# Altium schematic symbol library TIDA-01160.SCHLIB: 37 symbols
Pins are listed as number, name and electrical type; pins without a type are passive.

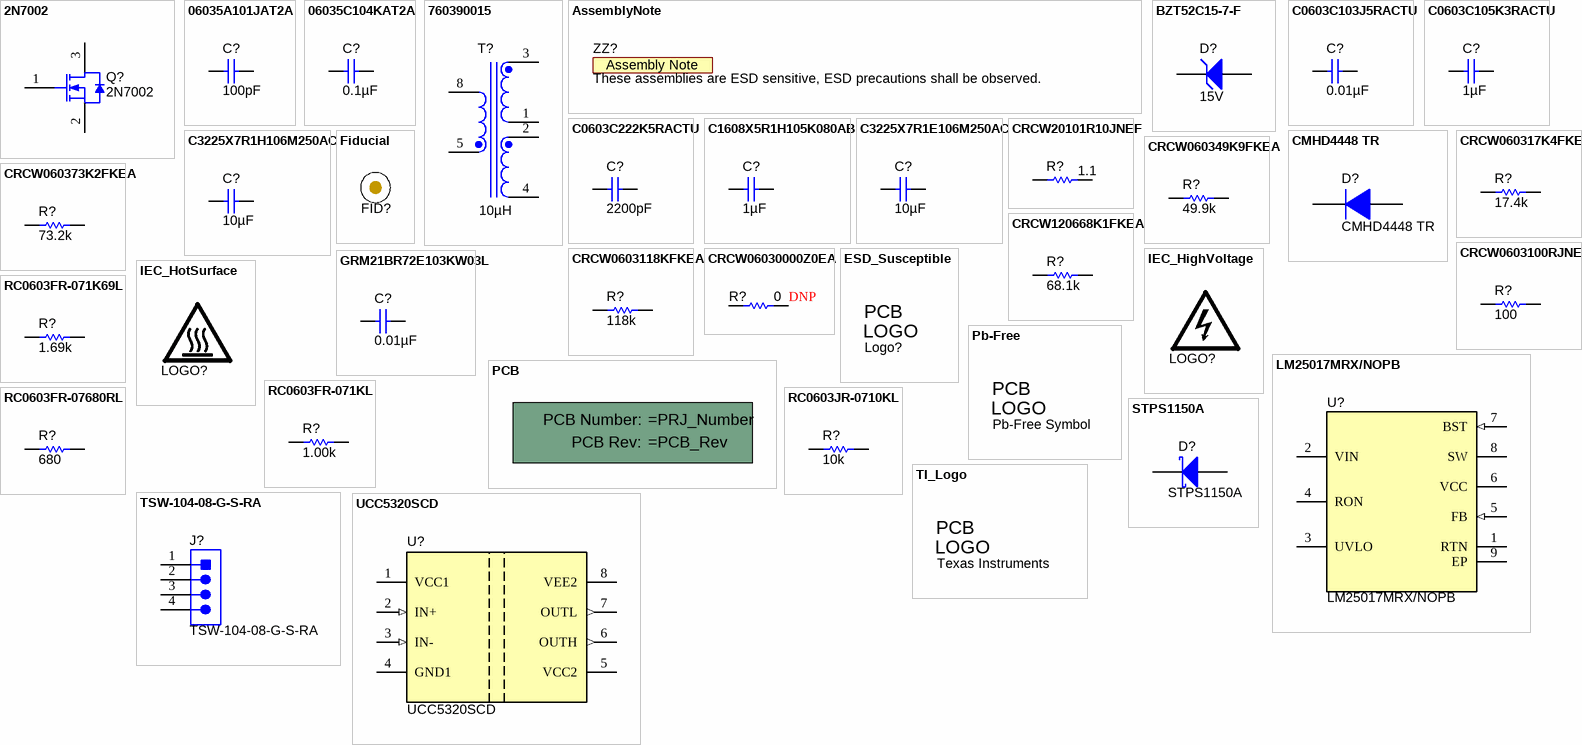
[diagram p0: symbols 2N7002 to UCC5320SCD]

## 2N7002
designator Q?
MOSFET, N-CH, 60 V, 115 A, SOT-23; Manufacturer: Fairchild Semiconductor; Alternate Manufacturer: None; U/M: EA; ChType: N; Value: 60V; VdsMax_V: 60; Value1: ? ohm; Value2: ? nC; Vgs_V: 20; IdsMax_A: 115; SizeAreaWB_mm2: 14; SizeArea_mm2: 7.5; SizeX_mm: 2.5; SizeY_mm: 3; SizeZ_mm: 1.1; AEC Category: Q101
footprint SOT-23
footprint SOT-23M
footprint SOT-23L
pins: 1 G, 2 S, 3 D

## 06035A101JAT2A
designator C?  ValueDisplayed: 100pF  (hidden comment: 06035A101JAT2A)
CAP, CERM, 100 pF, 50 V, +/- 5%, C0G/NP0, 0603; Manufacturer: AVX; Polarized: N; CompType: Capacitor; Value: 100pF; U/M: EA; Cap_F: 0.0000000001; Tolerance_%: 5; ESR_ohm: 0.119; Value1: 0.119 ohm; VDC_V: 50; Value2: 50V; TaMin_C: -55; TaMax_C: 125; Cap_Case: 0603; SizeArea_mm2: 1.28; SizeAreaWB_mm2: 4.68; SizeX_mm: 1.6; SizeY_mm: 0.8; SizeZ_mm: 1; AEC Category: Q200
signal-integrity model Cap
simulation model Cap
footprint 0603
footprint 0603M
footprint 0603L
footprint 0603_HV
footprint 0603S
pins: 1, 2

## 06035C104KAT2A
designator C?  ValueDisplayed: 0.1µF  (hidden comment: 06035C104KAT2A)
CAP, CERM, 0.1 µF, 50 V, +/- 10%, X7R, 0603; Manufacturer: AVX; Polarized: N; CompType: Capacitor; Value: 0.1uF; U/M: EA; Cap_F: 0.0000001; Tolerance_%: 10; Value1: Unknown; VDC_V: 50; Value2: 50V; TaMin_C: -55; TaMax_C: 125; Cap_Case: 0603; SizeArea_mm2: 1.28; SizeAreaWB_mm2: 4.68; SizeX_mm: 1.6; SizeY_mm: 0.8; SizeZ_mm: 1; AEC Category: Q200
signal-integrity model Cap
simulation model Cap
footprint 0603
footprint 0603M
footprint 0603L
footprint 0603_HV
footprint 0603S
pins: 1, 2

## 760390015
designator T?, comment ValueDisplayed: 10µH  (hidden comment: 750343468Rev02)
Transformer, 10µH, SMT; Manufacturer: Wurth Elektronik; SymbolCreator: Altium; Lp: 475; DCR_ohm: 0.35; Ns1toNp: 2; Rs1: 0.57
footprint WURTH_750315248 (TRANSFORMER, SMD-8P)
footprint WURTH_750315248 (Footprint not found)
pins: 1, 2, 3, 4, 5, 8

## AssemblyNote
designator ZZ?, comment These assemblies are ESD sensitive, ESD precautions shall be observed.  (no BOM)
SymbolCreator: codlsc; CompType: AssemblyNote
footprint AssemblyNote

## BZT52C15-7-F
designator D?  value 15V  (hidden comment: BZT52C15-7-F)
Diode, Zener, 15 V, 370 mW, AEC-Q101, SOD-123; Manufacturer: Diodes Inc.; SymbolCreator: a0412235; U/M: EA; Power_W: 0.37; Vz_V: 15; Value1: 0.37W; RJA_CperW: 338; AEC Category: Q101; AEC Qualified: Y
signal-integrity model Diode
footprint SOD-123
pins: 1 K, 2 A

## C0603C103J5RACTU
designator C?  ValueDisplayed: 0.01µF  (hidden comment: C0603C103J5RACTU)
CAP, CERM, 0.01 µF, 50 V, +/- 5%, X7R, 0603; Manufacturer: Kemet; Polarized: N; CompType: Capacitor; Value: 0.01uF; U/M: EA; Cap_F: 0.00000001; Tolerance_%: 5; Value1: Unknown; VDC_V: 50; Value2: 50V; TaMin_C: -55; TaMax_C: 125; Cap_Case: 0603; SizeArea_mm2: 1.28; SizeAreaWB_mm2: 4.68; SizeX_mm: 1.6; SizeY_mm: 0.8; SizeZ_mm: 1; AEC Category: Q200
signal-integrity model Cap
simulation model Cap
footprint 0603
footprint 0603M
footprint 0603L
footprint 0603_HV
footprint 0603S
pins: 1, 2

## C0603C105K3RACTU
designator C?  ValueDisplayed: 1µF  (hidden comment: C0603C105K3RACTU)
CAP, CERM, 1 µF, 25 V, +/- 10%, X7R, 0603; Manufacturer: Kemet; Polarized: N; CompType: Capacitor; Value: 1uF; U/M: EA; Cap_F: 0.000001; Tolerance_%: 10; Value1: Unknown; VDC_V: 25; Value2: 25V; TaMin_C: -55; TaMax_C: 125; Cap_Case: 0603; SizeArea_mm2: 1.28; SizeAreaWB_mm2: 4.68; SizeX_mm: 1.6; SizeY_mm: 0.8; SizeZ_mm: 1; AEC Category: Q200
signal-integrity model Cap
simulation model Cap
footprint 0603
footprint 0603M
footprint 0603L
footprint 0603_HV
footprint 0603S
pins: 1, 2

## C0603C222K5RACTU
designator C?  ValueDisplayed: 2200pF  (hidden comment: C0603C222K5RACTU)
CAP, CERM, 2200 pF, 50 V, +/- 10%, X7R, 0603; Manufacturer: Kemet; Polarized: N; CompType: Capacitor; Value: 2200pF; U/M: EA; Cap_F: 0.0000000022; Tolerance_%: 10; Value1: Unknown; VDC_V: 50; Value2: 50V; TaMin_C: -55; TaMax_C: 125; Cap_Case: 0603; SizeArea_mm2: 1.28; SizeAreaWB_mm2: 4.68; SizeX_mm: 1.6; SizeY_mm: 0.8; SizeZ_mm: 1; AEC Category: Q200
signal-integrity model Cap
simulation model Cap
footprint 0603
footprint 0603M
footprint 0603L
footprint 0603_HV
footprint 0603S
pins: 1, 2

## C1608X5R1H105K080AB
designator C?  ValueDisplayed: 1µF  (hidden comment: C1608X5R1H105K080AB)
CAP, CERM, 1 µF, 50 V, +/- 10%, X5R, 0603; Manufacturer: TDK; Polarized: N; CompType: Capacitor; Value: 1uF; U/M: EA; Cap_F: 0.000001; Tolerance_%: 10; ESR_ohm: 0.005522; Value1: 0.005522 ohm; VDC_V: 50; Value2: 50V; IRMS_A: 2.21617; TaMin_C: -55; TaMax_C: 85; Cap_Case: 0603; SizeArea_mm2: 1.28; SizeAreaWB_mm2: 4.68; SizeX_mm: 1.6; SizeY_mm: 0.8; SizeZ_mm: 1; AEC Category: Q200
signal-integrity model Cap
simulation model Cap
footprint 0603
footprint 0603M
footprint 0603L
footprint 0603_HV
footprint 0603S
pins: 1, 2

## C3225X7R1E106M250AC
designator C?  ValueDisplayed: 10µF  (hidden comment: C3225X7R1E106M250AC)
CAP, CERM, 10 µF, 25 V, +/- 20%, X7R, 1210; Manufacturer: TDK; Polarized: N; CompType: Capacitor; Value: 10uF; U/M: EA; Cap_F: 0.00001; Tolerance_%: 20; Value1: Unknown; VDC_V: 25; Value2: 25V; TaMin_C: -55; TaMax_C: 125; Cap_Case: 1210; SizeArea_mm2: 8; SizeAreaWB_mm2: 14.7; SizeX_mm: 3.2; SizeY_mm: 2.5; SizeZ_mm: 2.8; AEC Category: Q200
signal-integrity model Cap
simulation model Cap
footprint 1210_280
pins: 1, 2

## C3225X7R1H106M250AC
designator C?  ValueDisplayed: 10µF  (hidden comment: C3225X7R1H106M250AC)
CAP, CERM, 10 µF, 50 V, +/- 20%, X7R, 1210; Manufacturer: TDK; Polarized: N; CompType: Capacitor; Value: 10uF; U/M: EA; Cap_F: 0.00001; Tolerance_%: 20; Value1: Unknown; VDC_V: 50; Value2: 50V; TaMin_C: -55; TaMax_C: 125; Cap_Case: 1210; SizeArea_mm2: 8; SizeAreaWB_mm2: 14.7; SizeX_mm: 3.2; SizeY_mm: 2.5; SizeZ_mm: 2.8; AEC Category: Q200
signal-integrity model Cap
simulation model Cap
footprint 1210_280
pins: 1, 2

## CMHD4448 TR
designator D?
Diode, Switching, 100 V, 0.25 A, SOD-123; Manufacturer: Central Semiconductor; U/M: EA; Vf_V: 1; Value: 100V; Value1: 0.25A; Value2: 1V; Io_A: 0.25; Vr_V: 100; TJmax_C: 150; SizeAreaWB_mm2: 13.095; SizeArea_mm2: 6.545; SizeX_mm: 3.85; SizeY_mm: 1.7; SizeZ_mm: 1.35; AEC Category: Q101
signal-integrity model Diode
footprint SOD-123 (On Semi recommended land pattern)
pins: 1 K, 2 A

## CRCW20101R10JNEF
designator R?  ValueDisplayed: 1.1  (hidden comment: CRCW20101R10JNEF)
RES, 1.1, 5%, 0.75 W, AEC-Q200 Grade 0, 2010; Manufacturer: Vishay-Dale; CompType: Resistor; Value: 1.1; Value_Code: 1R10; Tolerance_%: 5; Power_W: 0.75; Value2: 0.75W; VDC_V: 400; TempCo: 200 ppm/C; SizeArea_mm2: 12.5; SizeY_mm: 2.5; SizeZ_mm: 1.66; EIA_Code: E24; U/M: EA; AEC Category: Q200; AEC Qualified: Y; AEC Grade: 0
signal-integrity model Resistor
simulation model Resistor
footprint 2010
footprint 2010M
footprint 2010L
pins: 1, 2

## CRCW060317K4FKEA
designator R?  ValueDisplayed: 17.4k  (hidden comment: CRCW060317K4FKEA)
RES, 17.4 k, 1%, 0.1 W, 0603; Manufacturer: Vishay-Dale; CompType: Resistor; Value: 17.4k; Res_ohm: 17400; Value_Code: 17k4; Tolerance_%: 1; Power_W: 0.1; Value2: 0.1W; VDC_V: 75; TempCo: 100 ppm/C; SizeArea_mm2: 1.28; SizeX_mm: 1.6; SizeY_mm: 0.8; EIA_Code: E96; U/M: EA; AEC Category: Q200
signal-integrity model Resistor
simulation model Resistor
footprint 0603
footprint 0603M
footprint 0603L
footprint 0603_HV
footprint 0603S
pins: 1, 2

## CRCW060349K9FKEA
designator R?  ValueDisplayed: 49.9k  (hidden comment: CRCW060349K9FKEA)
RES, 49.9 k, 1%, 0.1 W, 0603; Manufacturer: Vishay-Dale; CompType: Resistor; Value: 49.9k; Res_ohm: 49900; Value_Code: 49k9; Tolerance_%: 1; Power_W: 0.1; Value2: 0.1W; VDC_V: 75; TempCo: 100 ppm/C; SizeArea_mm2: 1.28; SizeX_mm: 1.6; SizeY_mm: 0.8; EIA_Code: E96; U/M: EA; AEC Category: Q200
signal-integrity model Resistor
simulation model Resistor
footprint 0603
footprint 0603M
footprint 0603L
footprint 0603_HV
footprint 0603S
pins: 1, 2

## CRCW060373K2FKEA
designator R?  ValueDisplayed: 73.2k  (hidden comment: CRCW060373K2FKEA)
RES, 73.2 k, 1%, 0.1 W, 0603; Manufacturer: Vishay-Dale; CompType: Resistor; Value: 73.2k; Res_ohm: 73200; Value_Code: 73k2; Tolerance_%: 1; Power_W: 0.1; Value2: 0.1W; VDC_V: 75; TempCo: 100 ppm/C; SizeArea_mm2: 1.28; SizeX_mm: 1.6; SizeY_mm: 0.8; EIA_Code: E96; U/M: EA; AEC Category: Q200
signal-integrity model Resistor
simulation model Resistor
footprint 0603
footprint 0603M
footprint 0603L
footprint 0603_HV
footprint 0603S
pins: 1, 2

## CRCW120668K1FKEA
designator R?  ValueDisplayed: 68.1k  (hidden comment: CRCW120668K1FKEA)
RES, 68.1 k, 1%, 0.25 W, 1206; Manufacturer: Vishay-Dale; CompType: Resistor; Value: 68.1k; Res_ohm: 68100; Value_Code: 68k1; Tolerance_%: 1; Power_W: 0.25; Value2: 0.25W; VDC_V: 200; TempCo: 100 ppm/C; SizeArea_mm2: 5.12; SizeX_mm: 3.2; SizeY_mm: 1.6; SizeZ_mm: 1.35; EIA_Code: E96; U/M: EA; AEC Category: Q200
signal-integrity model Resistor
simulation model Resistor
footprint 1206
footprint 1206M
footprint 1206L
pins: 1, 2

## CRCW0603100RJNEA
designator R?  ValueDisplayed: 100  (hidden comment: CRCW0603100RJNEA)
RES, 100, 5%, 0.1 W, 0603; Manufacturer: Vishay-Dale; CompType: Resistor; Value: 100; Value_Code: 100R; Tolerance_%: 5; Power_W: 0.1; Value2: 0.1W; VDC_V: 75; TempCo: 200 ppm/C; SizeArea_mm2: 1.28; SizeX_mm: 1.6; SizeY_mm: 0.8; SizeZ_mm: 1; EIA_Code: E24; U/M: EA; AEC Category: Q200
signal-integrity model Resistor
simulation model Resistor
footprint 0603
footprint 0603M
footprint 0603L
footprint 0603_HV
footprint 0603S
pins: 1, 2

## CRCW0603118KFKEA
designator R?  ValueDisplayed: 118k  (hidden comment: CRCW0603118KFKEA)
RES, 118 k, 1%, 0.1 W, 0603; Manufacturer: Vishay-Dale; CompType: Resistor; Value: 118k; Res_ohm: 118000; Tolerance_%: 1; Power_W: 0.1; Value2: 0.1W; VDC_V: 75; TempCo: 100 ppm/C; SizeArea_mm2: 1.28; SizeX_mm: 1.6; SizeY_mm: 0.8; EIA_Code: E96; U/M: EA; AEC Category: Q200
signal-integrity model Resistor
simulation model Resistor
footprint 0603
footprint 0603M
footprint 0603L
footprint 0603_HV
footprint 0603S
pins: 1, 2

## CRCW06030000Z0EA
designator R?  ValueDisplayed: 0  Installation: DNP  (hidden comment: CRCW06030000Z0EA)
RES, 0, 5%, 0.1 W, 0603; Manufacturer: Vishay-Dale; CompType: Resistor; Value: 0; Value_Code: 0000; Tolerance_%: 5; Power_W: 0.1; Value2: 0.1W; VDC_V: 75; TempCo: 200 ppm/C; EIA_Code: E24; U/M: EA; AEC Category: Q200
signal-integrity model Resistor
simulation model Resistor
footprint 0603 (0603 from SM-752 data)
footprint 0603M
footprint 0603L
footprint 0603_HV
footprint 0603S
pins: 1, 2

## ESD_Susceptible
designator Logo?, comment ESD Susceptible  (value not drawn)  (no BOM)
ESD Susceptible Symbol; SymbolCreator: a0412235
footprint ESD_Overlay_Large
footprint ESD_Overlay_Medium
footprint ESD_Overlay_Small

## Fiducial
designator FID?  (value not drawn)
Fiducial mark.  There is nothing to buy or mount.; SymbolCreator: codlsc
footprint Fiducial10-30
footprint Fiducial10-20
footprint Fiducial15-30
footprint Fiducial20-40
footprint Fiducial6.4-20

## GRM21BR72E103KW03L
designator C?  ValueDisplayed: 0.01µF  (hidden comment: GRM21BR72E103KW03L)
CAP, CERM, 0.01 µF, 250 V, +/- 10%, X7R, 0805; Manufacturer: MuRata; Polarized: N; CompType: Capacitor; Value: 0.01uF; U/M: EA; Cap_F: 0.00000001; Tolerance_%: 10; Value1: Unknown; VDC_V: 250; Value2: 250V; TaMin_C: -55; TaMax_C: 125; Cap_Case: 0805; SizeArea_mm2: 2.5; SizeAreaWB_mm2: 6.75; SizeX_mm: 2; SizeY_mm: 1.25; SizeZ_mm: 1.45; AEC Category: Q200
signal-integrity model Cap
simulation model Cap
footprint 0805_HV
footprint 0805_HV1
footprint 0805
footprint 0805M
footprint 0805L
pins: 1, 2

## IEC_HighVoltage
designator LOGO?, comment DANGER HIGH VOLTAGE  (value not drawn)  (no BOM)
IEC 61010-1 High Voltage Warning; SymbolCreator: a0412235
footprint IEC_HighVoltage_Large
footprint IEC_HighVoltage_Medium
footprint IEC_HighVoltage_Small

## IEC_HotSurface
designator LOGO?, comment CAUTION HOT SURFACE  (value not drawn)  (no BOM)
IEC 61010-1 Hot Surface Warning; SymbolCreator: a0412235
footprint IEC_HotSurface_Large
footprint IEC_HotSurface_Medium
footprint IEC_HotSurface_Small

## LM25017MRX/NOPB
designator U?
48V, 650mA Constant On-Time Synchronous Buck Regulator, DDA0008B; Alternate PartNumber: LM25017MR/NOPB; Manufacturer: Texas Instruments; SymbolCreator: a0412235; SizeArea_mm2: 31; SizeAreaWB_mm2: 57.4; SizeX_mm: 5; SizeY_mm: 6.2; SizeZ_mm: 1.7; CompType: IC; U/M: EA
footprint DDA0008B_N
footprint DDA0008B_M
footprint DDA0008B_L
pins: 1 RTN (power), 2 VIN (power), 3 UVLO, 4 RON, 5 FB (in), 6 VCC (power), 7 BST (in), 8 SW (power), 9 EP (power)

## Pb-Free
designator Logo?, comment Pb-Free Symbol  (no BOM)
SymbolCreator: a0412235
footprint Pb-Free_Overlay_Medium
footprint Pb-Free_Overlay_Small

## PCB
designator !PCB?, comment Printed Circuit Board  (value not drawn)  (mechanical)
Manufacturer: Any; SymbolCreator: a0412235; CompType: PCB
1 alternate drawing of the same symbol

## RC0603FR-071K69L
designator R?  ValueDisplayed: 1.69k  (hidden comment: RC0603FR-071K69L)
RES, 1.69 k, 1%, 0.1 W, 0603; Manufacturer: Yageo America; CompType: Resistor; Value: 1.69k; Res_ohm: 1690; Value_Code: 1k69; Tolerance_%: 1; Power_W: 0.1; Value2: 0.1W; VDC_V: 150; TempCo: 200 ppm/C; SizeArea_mm2: 1.28; SizeX_mm: 1.6; SizeY_mm: 0.8; EIA_Code: E96; U/M: EA; AEC Category: Q200
signal-integrity model Resistor
simulation model Resistor
footprint 0603
footprint 0603M
footprint 0603L
footprint 0603_HV
footprint 0603S
pins: 1, 2

## RC0603FR-071KL
designator R?  ValueDisplayed: 1.00k  (hidden comment: RC0603FR-071KL)
RES, 1.00 k, 1%, 0.1 W, 0603; Manufacturer: Yageo America; CompType: Resistor; Value: 1.00k; Res_ohm: 1000; Value_Code: 1k00; Tolerance_%: 1; Power_W: 0.1; Value2: 0.1W; VDC_V: 150; TempCo: 200 ppm/C; SizeArea_mm2: 1.28; SizeX_mm: 1.6; SizeY_mm: 0.8; EIA_Code: E96; U/M: EA; AEC Category: Q200
signal-integrity model Resistor
simulation model Resistor
footprint 0603
footprint 0603M
footprint 0603L
footprint 0603_HV
footprint 0603S
pins: 1, 2

## RC0603FR-07680RL
designator R?  ValueDisplayed: 680  (hidden comment: RC0603FR-07680RL)
RES, 680, 1%, 0.1 W, 0603; Manufacturer: Yageo America; CompType: Resistor; Value: 680; Value_Code: 680R; Tolerance_%: 1; Power_W: 0.1; Value2: 0.1W; VDC_V: 150; TempCo: 200 ppm/C; SizeArea_mm2: 1.28; SizeX_mm: 1.6; SizeY_mm: 0.8; U/M: EA; AEC Category: Q200
signal-integrity model Resistor
simulation model Resistor
footprint 0603
footprint 0603M
footprint 0603L
footprint 0603_HV
footprint 0603S
pins: 1, 2

## RC0603JR-0710KL
designator R?  ValueDisplayed: 10k  (hidden comment: RC0603JR-0710KL)
RES, 10 k, 5%, 0.1 W, 0603; Manufacturer: Yageo America; CompType: Resistor; Value: 10k; Res_ohm: 10000; Value_Code: 10k0; Tolerance_%: 5; Power_W: 0.1; Value2: 0.1W; VDC_V: 50; TempCo: 100 ppm/C; SizeArea_mm2: 1.28; SizeX_mm: 1.6; SizeY_mm: 0.8; SizeZ_mm: 1; EIA_Code: E24; U/M: EA; AEC Category: Q200
signal-integrity model Resistor
simulation model Resistor
footprint 0603
footprint 0603M
footprint 0603L
footprint 0603_HV
footprint 0603S
pins: 1, 2

## STPS1150A
designator D?
Diode, Schottky, 150 V, 1 A, SMA; Manufacturer: STMicroelectronics; U/M: EA; Vf_V: 0.78; Value: 150V; Value1: 1A; Value2: 0.78V; Io_A: 1; Vr_V: 150; TJmax_C: 175; RJC_CperW: 30; SizeAreaWB_mm2: 37.3428; SizeArea_mm2: 16.3228; SizeX_mm: 5.59; SizeY_mm: 2.92; SizeZ_mm: 2.87; AEC Category: Q101; AEC Qualified: N
signal-integrity model Diode
footprint SMA
pins: 1 K, 2 A

## TI_Logo
designator Logo?, comment Texas Instruments  (no BOM)
Texas Instrument Corporate Signature; SymbolCreator: codlsc
footprint TI_Stacked_SolderMask_Medium
footprint TI_Stacked_SolderMask_Small
footprint TI_Stacked_Overlay_Medium
footprint TI_Stacked_Overlay_Small
footprint TI_Horizontal_SolderMask_Medium
footprint TI_Horizontal_SolderMask_Small
footprint TI_Horizontal_Overlay_Medium
footprint TI_Horizontal_Overlay_Small
footprint TI_Symbol_SolderMask_Small
footprint TI_Symbol_Overlay_Medium
footprint TI_Symbol_Overlay_Small
footprint TI_Symbol_SolderMask_Medium

## TSW-104-08-G-S-RA
designator J?
Header, 100mil, 4x1, Gold, R/A, TH; Manufacturer: Samtec; SymbolCreator: a0412235; Pitch_mm: 2.54; Gender: Male; Shrouded: N; Row_Count: 1; Current_A: 6.3; Voltage_V: 550; Cert_CSA: Y
footprint TSW-104-08-G-S-RA
pins: 1, 2, 3, 4

## UCC5320SCD
designator U?
Isolated Gate Drivers with High CMTI and Scalable Drive Strength, D0008B (SOIC-8); Manufacturer: Texas Instruments; SymbolCreator: a0411947; SizeArea_mm2: 29.4; SizeAreaWB_mm2: 55.2; SizeX_mm: 6; SizeY_mm: 4.9; SizeZ_mm: 1.75; CompType: IC; U/M: EA
footprint D0008B_HV
footprint D0008B_N
footprint D0008B_M
footprint D0008B_L
pins: 1 VCC1 (power), 2 IN+ (in), 3 IN- (in), 4 GND1 (power), 5 VCC2 (power), 6 OUTH (out), 7 OUTL (out), 8 VEE2 (power)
